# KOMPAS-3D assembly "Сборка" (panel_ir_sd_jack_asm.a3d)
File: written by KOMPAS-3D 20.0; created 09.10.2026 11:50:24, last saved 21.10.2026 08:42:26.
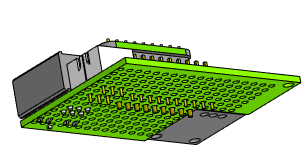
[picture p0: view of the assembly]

Document properties: Полное имя файла: D:\RicWork\Project-EPS32\box_compas\сборки компонентов\panel_ir_sd_jack_asm.a3d

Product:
- Part/product: Сборка
    Масса: 0.0501572
  - Component [detail]: Деталь  | Масса: 0.00130352; source file: ..\разъемы\pls_10.m3d
  - Component [detail]: Деталь  | Масса: 0.00277694; source file: ..\разъемы\pbs_9.m3d
  - Component [detail]: Деталь  | Масса: 0.0153693; source file: ..\макетки\Макетная плата_03.m3d
  - Component [detail]: Деталь  | Масса: 0.00363733; source file: ..\IR\ir_tzt.m3d
  - Component [detail]: Деталь  | Масса: 0.0149267; source file: ..\разъемы\PJ-306BM.m3d
  - Component [assembly]: Сборка  | Масса: 0.00979968; source file: ..\SD card\Adafruit_Micro_SD_SPI_or_SDIO asm.a3d
  - Component [detail]: Деталь  | qty 2  | Масса: 0.00117184; source file: ..\разъемы\B3B-XH-A.m3d

Referenced files in D:\RicWork\Project-EPS32\box_compas\макетки\: Макетная плата_03.m3d
Referenced files in D:\RicWork\Project-EPS32\box_compas\IR\: ir_tzt.m3d
Referenced files in D:\RicWork\Project-EPS32\box_compas\разъемы\: pbs_9.m3d, B3B-XH-A.m3d, PJ-306BM.m3d, pls_10.m3d
Referenced files in D:\RicWork\Project-EPS32\box_compas\SD card\: Adafruit_Micro_SD_SPI_or_SDIO asm.a3d
Referenced files in D:\myProjects\Progect_esp32\box_compas\разъемы\: B3B-XH-A.m3d
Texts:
  Деталь (1)
  Деталь (2)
